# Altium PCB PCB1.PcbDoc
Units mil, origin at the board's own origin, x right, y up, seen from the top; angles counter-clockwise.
Board outline 3995.98 x 2559.06 mil, 2 copper layers (Top Layer, Bottom Layer); 28 components, 42 nets, 154 pads, 4 vias.
Unrouted connection lines stored in the file: 6.
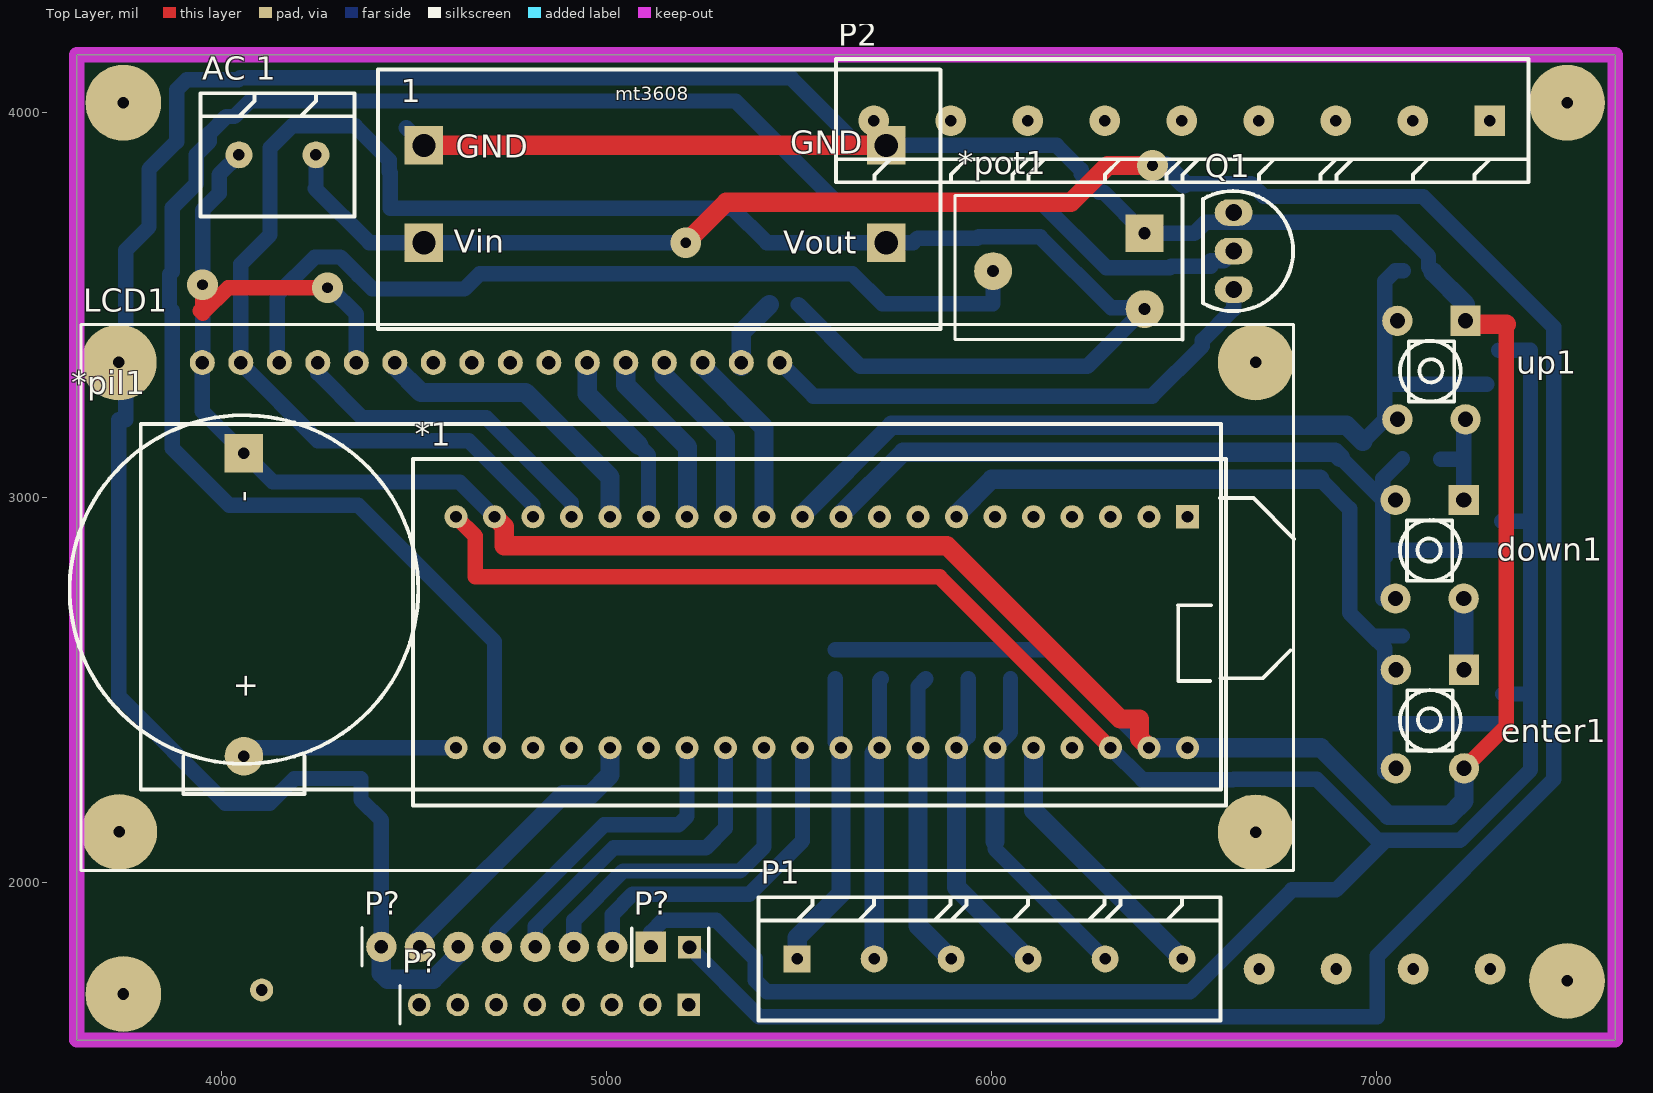
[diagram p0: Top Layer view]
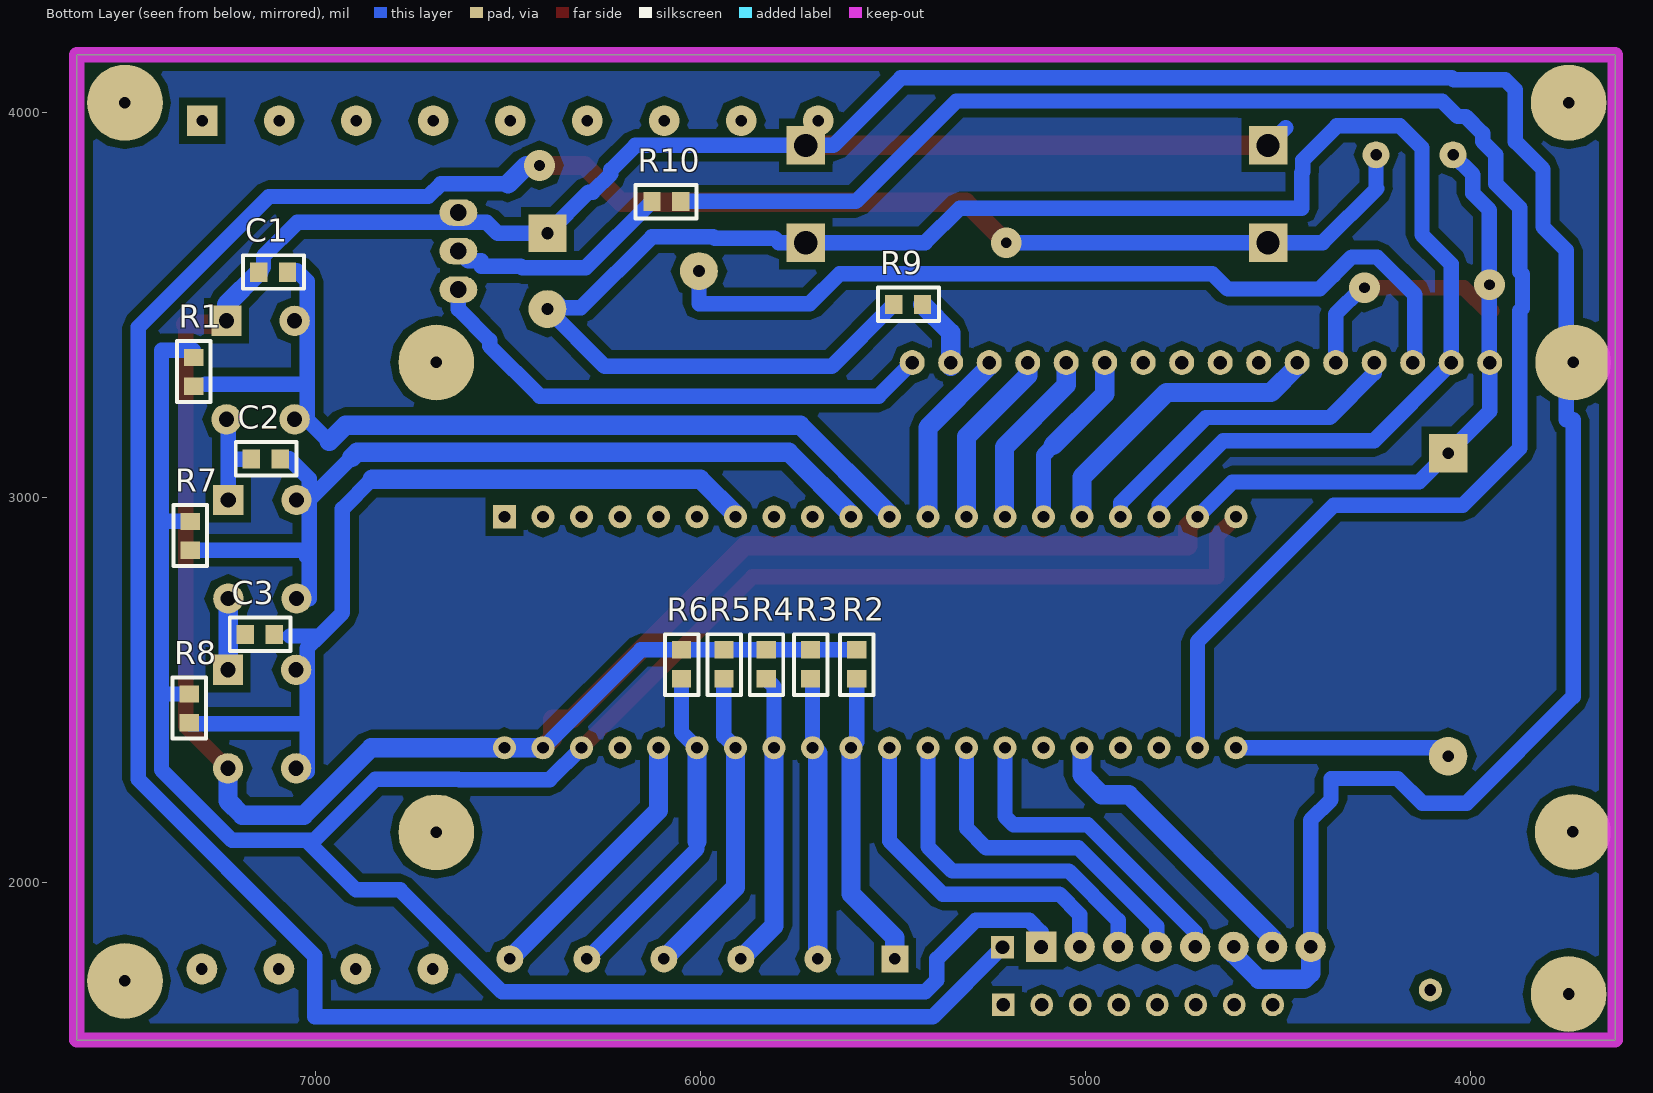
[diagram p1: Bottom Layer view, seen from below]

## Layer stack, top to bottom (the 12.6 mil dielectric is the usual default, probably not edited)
Top Solder: solder mask 0.4, Solder Resist, Dk 3.5
Top Layer: signal copper 1.4
Dielectric 1: dielectric 12.6, FR-4, Dk 4.8
Bottom Layer: signal copper 1.4
Bottom Solder: solder mask 0.4, Solder Resist, Dk 3.5

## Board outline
3624.02,1590.55 3624.02,4149.61 7620,4149.61 7620,1590.55

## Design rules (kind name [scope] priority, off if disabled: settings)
Clearance [All] p1: gap=20
PolygonConnect [All] p1: connectstyle=Relief reliefconductorwidth=10 reliefentries=4 polygonreliefangle="90 Angle" airgapwidth=10
RoutingVias [All] p1: holewidth=28 width=50 viastyle="Through Hole" minholewidth=28 minwidth=50 maxholewidth=28 maxwidth=50
SolderMaskExpansion [All] p1: expansion=4
Width [All] p1: maxlimit=50 minlimit=40 preferedwidth=50
30 further rules are at their usual default settings.

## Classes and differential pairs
component class Sheet2: *1 *pil1 *pot1 C1 C2 C3 down1 enter1 LCD1 P1 P2 P? Q1 R1 R2 R3 R4 R5 R6 R7 R8 R9 R10 up1

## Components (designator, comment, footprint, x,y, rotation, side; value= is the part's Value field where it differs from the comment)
1 "" mt3608 4525.59,3661.42 r0 top
*1 "stm32_blue_pill" STM32_BLUE_PIL 5809.06,2649.61 r180 top
*pil1 "cr2032pil_soket" "cr2032 holder" 4058.23,3115 r270 top
*pot1 "trimpot" trimpot 6397.64,3686.02 r270 top
"AC 1" "" "klemens 200 mil" 4045.28,3889.76 r0 top
C1 "Cap Pol3" "Resistor smd" 7110,3585 r0 bottom
C2 "Cap Pol3" "Resistor smd" 7128.94,3099.41 r0 bottom
C3 "Cap Pol3" "Resistor smd" 7144.69,2643.7 r0 bottom
down1 "buttun 4 pin" button 7137.8,2865.16 r270 top
enter1 "buttun 4 pin" button 7138.78,2424.21 r270 top
LCD1 "162A" lcd_benim_kullndigim 3950,3350 r0 top
P1 "Header 6" "klemens 6X" 5495.08,1801.18 r0 top
P2 "Header 9" "klemens 9X" 7294.29,3978.35 r180 top
P? "Header 8" HDR1X8#1 5213.58,1682.09 r180 top
P? "Header 2" HDR1X2 5215.55,1831.69 r180 top
P? "Header 8" HDR1X8#2 5115.16,1832.68 r180 top
Q1 "BC337" bc337 6628.94,3639.76 r270 top
R1 "Res1" "Resistor smd" 7315.94,3325.79 r270 bottom
R2 "Res1" "Resistor smd" 5594.17,2566.42 r90 bottom
R3 "Res1" "Resistor smd" 5714.17,2566.42 r90 bottom
R4 "Res1" "Resistor smd" 5829.17,2566.42 r90 bottom
R5 "Res1" "Resistor smd" 5939.17,2566.42 r90 bottom
R6 "Res1" "Resistor smd" 6049.17,2566.42 r90 bottom
R7 "Res1" "Resistor smd" 7325,2900 r270 bottom
R8 "Res1" "Resistor smd" 7327.76,2451.77 r270 bottom
R9 "Res1" "Resistor smd" 5460.63,3500.98 r0 bottom
R10 "Res1" "Resistor smd" 6088.58,3768.7 r180 bottom
up1 "buttun 4 pin" button 7142.72,3330.71 r270 top

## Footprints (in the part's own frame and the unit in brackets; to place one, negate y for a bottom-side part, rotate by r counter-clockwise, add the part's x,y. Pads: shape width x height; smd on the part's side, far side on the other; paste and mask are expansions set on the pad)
bc337 [mm]
  oval 1.75x2.5 hole 1.1: 1(-2.54,0) 2(0,0) 3(2.54,0)
  silkscreen extent -3.96,-2.03 3.96,3.92
button [mm]
  rect 2x2 hole 1: 1(-3.25,2.25)
  round 2 hole 1: 2(-3.25,-2.25) 3(3.25,2.25) 4(3.25,-2.25)
  silkscreen extent -1.9,-1.5 2.08,1.5
"cr2032 holder" [mil]
  rect 100x100 hole 30: 1(0,0)
  round 100 hole 30: 2(787.4,0)
  silkscreen extent -98,-453 886,453
HDR1X2 [mm] "Connector; Header; 2 Position"
  rect 1.5x1.5 hole 0.9: 1(0,0)
  round 1.5 hole 0.9: 2(2.54,0)
  silkscreen extent -1.27,-1.27 3.81,1.27
HDR1X8#1 [mm] "Connector; Header; 8 Position"
  rect 1.5x1.5 hole 0.9: 1(0,0)
  round 1.5 hole 0.9: 2(2.54,0) 3(5.08,0) 4(7.62,0) 5(10.16,0) 6(12.7,0) 7(15.24,0) 8(17.78,0)
  silkscreen extent 19.05,-1.27 19.05,1.27
HDR1X8#2 [mm] "Connector; Header; 8 Position"
  rect 2x2 hole 0.9: 1(0,0)
  round 2 hole 0.9: 2(2.54,0) 3(5.08,0) 4(7.62,0) 5(10.16,0) 6(12.7,0) 7(15.24,0) 8(17.78,0)
  silkscreen extent 19.05,-1.27 19.05,1.27
"klemens 6X" [mil]
  rect 70x70 hole 30: 1(0,0)
  round 70 hole 30: 2(200,0) 3(400,0) 4(600,0) 5(800,0) 6(1000,0)
  silkscreen extent -100,-160 1100,160
"klemens 9X" [mil]
  rect 80x80 hole 30: 1(0,0)
  round 80 hole 30: 2(200,0) 3(400,0) 4(600,0) 5(800,0) 6(1000,0) 7(1200,0) 8(1400,0) 9(1600,0)
  silkscreen extent -100,-160 1698,160
"klemens 200 mil" [mil]
  round 70 hole 30: 1(0,0) 2(200,0)
  silkscreen extent -100,-160 300,160
lcd_benim_kullndigim [mil]
  round 65 hole 35.43: 1(0,0) 2(100,0) 3(200,0) 4(300,0) 5(400,0) 6(500,0) 7(600,0) 8(700,0) 9(800,0) 10(900,0) 11(1000,0) 12(1100,0) 13(1200,0) 14(1300,0) 15(1400,0) 16(1500,0)
  silkscreen extent -315,-1319 2836,98
mt3608 [mil] "ayarlý regulatör"
  rect 100x100 hole 60: 1(0,0) 2(0,253) 3(1201,253) 4(1201,0)
  silkscreen extent -119,-224 1342,450
"Resistor smd" [mil]
  rect 45x50 smd: 1(-37.5,0) 2(37.5,0)
  silkscreen extent -80,-44 78,43
STM32_BLUE_PIL [mil] "arduino nano"
  rect 60x60 hole 30: 0(-700,-300)
  round 60 hole 30: 1(-600,-300) 2(-500,-300) 3(-400,-300) 4(-300,-300) 5(-200,-300) 6(-100,-300) 7(0,-300) 8(100,-300) 9(200,-300) 10(300,-300) 11(400,-300) 12(500,-300) 13(600,-300) 14(700,-300) 15(800,-300) 16(900,-300) 17(1000,-300) 18(1100,-300) 19(1200,-300) 20(1200,300) 21(1100,300) 22(1000,300) 23(900,300) 24(800,300) 25(700,300) 26(600,300) 27(500,300) 28(400,300) 29(300,300) 30(200,300) 31(100,300) 32(0,300) 33(-100,300) 34(-200,300) 35(-300,300) 36(-400,300) 37(-500,300) 38(-600,300) 39(-700,300)
  silkscreen extent -800,-450 1312,450
trimpot [mm]
  rect 2.5x2.5 hole 0.8: 1(0,0)
  round 2.5 hole 0.8: 2(2.5,-10) 3(5,0)
  silkscreen extent -2.5,-12.5 7,2.5

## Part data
1: library part "swich up adj regulator modul"
"AC 1": library part klemens2li
C1 C2 C3: "Polarized Capacitor (Surface Mount)"
LCD1: "16 char * 2 line LCD character display with b/light"
P1: "Header, 6-Pin"
P2: "Header, 9-Pin"
P? P?: "Header, 8-Pin"
P?: "Header, 2-Pin"
Q1: "NPN General Purpose Amplifier"
R1 R2 R3 R4 R5 R6 R7 R8 R9 R10: "Resistor"

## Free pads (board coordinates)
  round 196.85 hole 30: 0(7495,4025) 1(7495.08,1744.09) 2(3745,1710) 3(3745,4025) 4(6686.02,2129.92) 5(3734.25,2130.91) 6(3733.27,3350.39) 9(6686.02,3350.39)
  round 80 hole 30: 12(7295,1775) 13(7095,1775) 14(6895,1775) 15(6695,1775)
  round 60 hole 30: 13(4104.33,1720.47)

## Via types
v1: diameter 80, hole 28, Top Layer to Bottom Layer, 4 vias

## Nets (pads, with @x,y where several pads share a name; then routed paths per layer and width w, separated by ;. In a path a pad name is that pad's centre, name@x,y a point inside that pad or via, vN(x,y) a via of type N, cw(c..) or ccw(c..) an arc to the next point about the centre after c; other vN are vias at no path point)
BUTTON_DOWN: *1.9 C2.1 down1.2 down1.4 R7.2 | length 2227.6
  Bottom Layer w40: 6906.02,3103.35 down1.2@7016.42,2992.95 ; down1.4@7016.42,2737.05 7016.42,2855 ; 7023.92,2847.5 7016.42,2855 ; 7023.92,2862.5 R7.2 ; 7067.5,3100 7016.42,3048.92 down1.2@7016.42,2992.95 ; 7016.42,2855 down1.2@7016.42,2992.95
  Bottom Layer w50: *1.9 5609.06,2955.67 5770.63,3117.24 6892.13,3117.24 6906.02,3103.35
BUTTON_ENTER: *1.6 C3.1 enter1.2 enter1.4 R8.2 | length 2200.9
  Bottom Layer w40: 6852.76,3047.24 6930,2970 6930,2700 6990,2640 ; enter1.4@7021.42,2287.05 7021.42,2410 ; 7067.5,2640 6990,2640 ; R8.2@7325.98,2412.5 7023.92,2412.5 7021.42,2410 ; 6990,2640 7021.42,2608.58 7021.42,2410
  Bottom Layer w50: *1.6 5909.06,2955.67 6000.63,3047.24 6852.76,3047.24
BUTTON_UP: *1.10 C1.1 R1.2 up1.2 up1.4 | length 2336.3
  Bottom Layer w40: 6964.37,3145 7021.42,3202.05 7021.42,3561.42 7048.58,3588.58 C1.1@7068.92,3588.58 ; 7026.42,3300 7032.13,3294.29 7286.79,3294.29
  Bottom Layer w50: *1.10 5509.06,2955.67 5740.63,3187.24 6922.13,3187.24 6964.37,3145
DEV_POMP_ROLE: *1.24 P?.7 | length 763
  Bottom Layer w50: P?.7@4515.16,1832.68 4515.16,1855.71 4887.3,2227.85 4958.17,2227.85 5009.06,2278.74 *1.24
DIREK_DEV_POMP_ROLE: *1.29 P?.2@5015.16,1832.68 P?.2@5113.58,1682.09 | length 899
  Bottom Layer w40: P?.2@5015.16,1832.68 5015.16,1916.64 5067.97,1969.45 5371.02,1969.45 5509.06,2107.48 *1.29
DIREK_DEVRE_NTC: *1.30 P1.1 R2.1 | length 781.1
  Bottom Layer w40: R2.1 5594.17,2364.49 *1.30
  Bottom Layer w50: P1.1 5495.08,1856.5 5609.06,1970.47 *1.30
DIS_HAVA_NTC: *1.34 P1.5 R6.1 | length 862.8
  Bottom Layer w40: 6009.06,2106.3 6009.06,2087.2 P1.5 ; *1.34 6049.17,2389.72 R6.1
  Bottom Layer w50: 6009.06,2106.3 *1.34
GND: 1.2 1.3 "AC 1.1" *1.18 *1.38 *1.39 *pil1.1 *pot1.1 C1.2 enter1.3 LCD1.1 LCD1.5 P?.6@4615.16,1832.68 P?.8@4415.16,1832.68 pad.6 Q1.1 R2.2 R3.2 R4.2 R5.2 R6.2 up1.1 | length 15622.4
  Top Layer w40: v1(3950.79,3552.17) 3950.79,3490.16 3944.88,3484.25 3950.79,3478.35 4016.73,3544.29 v1(4275.59,3544.29) ; enter1.3 7337.05,2405.94 7337.05,3449.8
  Top Layer w50: 1.2 1.3 ; *1.18 4734.06,2924.61 4734.06,2874.61 5884.06,2874.61 6334.06,2424.61 6384.06,2424.61 6384.06,2374.61 *1.38 ; up1.1 7240.16,3449.8 7337.05,3449.8
  Bottom Layer w40: LCD1.1@3945.87,3354.13 3944.88,3355.12 3950.79,3361.02 v1(3950.79,3552.17) 3950.79,3746.21 3993.88,3789.3 3993.88,3838.37 4045.28,3889.76 ; LCD1.1 3950,3223.23 *pil1.1 4133.27,3039.96 4618.7,3039.96 *1.18 ; v1(4275.59,3544.29) 4281.5,3544.29 4350,3475.79 LCD1.5 ; P?.8@4415.16,1832.68 4415.16,2161.42 4362.2,2214.37 4362.2,2269.68 4189.17,2269.68 4125,2205.51 4010.04,2205.51 3733.27,2482.28 3733.27,3201.77 3750.98,3201.77 3750.98,3641.73 3811.69,3702.44 3811.69,3852.46 3883.43,3924.19 3883.43,4058.58 3909.49,4084.65 4043.88,4084.65 4048.84,4089.61 5479.69,4089.61 5654.87,3914.42 1.3 6169.24,3914.42 6232.99,3850.67 6232.99,3839.89 6279.86,3793.03 6290.63,3793.03 *pot1.1 6526.96,3686.02 6555.15,3714.21 7047.36,3714.21 7135,3626.57 7135,3597.5 C1.2 ; 1.2@4479.46,3960.55 1.2 ; R2.2 R3.2 R4.2 R5.2 R6.2 6154.74,2603.92 *1.38
  Bottom Layer w50: P?.8@4415.16,1832.68 4415.16,1763.94 4430.79,1748.31 4550.1,1748.31 4615.16,1813.36 P?.6@4615.16,1832.68 ; *1.38 *1.39 6855.12,2349.61 7030.51,2174.21 7189.96,2174.21 7227.36,2211.61 enter1.3 ; C1.2 7231.3,3501.2 up1.1
JD_VCC: 1.1 "AC 1.2" P?.1@5215.55,1831.69 | length 7460.8
  Top Layer w50: v1(5205.71,3661.42) 5311.02,3766.73 6206.69,3766.73 6302.17,3862.2 v1(6418.31,3862.2)
  Bottom Layer w40: 4243.31,3802.17 4384.06,3661.42 1.1 v1(5205.71,3661.42) ; 4245.28,3804.13 4245.28,3889.76 ; P?.1@5215.55,1831.69 5396.69,1650.55 7001.97,1650.55 7001.97,1809.44 7460,2267.47 7460,3442.5 7121.03,3781.47 6707.28,3781.47 6674.54,3814.21 6500,3814.21
  Bottom Layer w50: v1(6418.31,3862.2) 6452.01,3862.2 6500,3814.21
KARISIM_NTC: *1.32 P1.3 R4.1 | length 771.7
  Bottom Layer w40: *1.32 5809.06,2508.8 R4.1
  Bottom Layer w50: *1.32 5809.06,1887.2 P1.3
KAZAN_NTC: *1.33 P1.4 R5.1 | length 817.3
  Bottom Layer w40: *1.33 5939.17,2379.72 R5.1
  Bottom Layer w50: *1.33 5909.06,1987.2 P1.4
KAZAN_ROLE: *1.25
LCD_LED: *1.21 R10.2 | length 4410.3
  Bottom Layer w40: *1.21 4709.06,2625.59 4354.69,2979.96 4019.69,2979.96 3871.69,3127.95 3871.69,3484.66 3864.88,3491.47 3864.88,3579.4 3871.69,3586.21 3871.69,3751.97 3933.88,3814.15 3933.88,3889.79 3968.31,3924.22 3968.31,3945.44 4012.24,3989.37 4033.45,3989.37 4073.69,4029.61 5335.55,4029.61 5596.46,3768.7 R10.2
Net*1_11: *1.11 LCD1.14 | length 456.7
  Bottom Layer w50: LCD1.14@5250,3340.4 5409.06,3181.34 *1.11
Net*1_12: *1.12 LCD1.13 | length 456.7
  Bottom Layer w50: LCD1.13@5150,3340.4 5150,3316.54 5309.06,3157.48 *1.12
Net*1_13: *1.13 LCD1.12 | length 467.6
  Bottom Layer w50: LCD1.12 5050,3291.71 5210.63,3131.08 5210.63,2951.18 *1.13
Net*1_14: *1.14 LCD1.11 | length 466.3
  Bottom Layer w40: 5084.06,3134.45 5109.06,3109.45 *1.14
  Bottom Layer w50: LCD1.11 4950,3268.5 5084.06,3134.45
Net*1_15: *1.15 LCD1.6 | length 791.1
  Bottom Layer w50: LCD1.6 4450,3340.4 4517.9,3272.5 4789.51,3272.5 5009.06,3052.95 *1.15
Net*1_16: *1.16 LCD1.4 | length 862
  Bottom Layer w40: LCD1.4 4250,3322.66 4365.16,3207.5 4687.19,3207.5 4909.06,2985.63 *1.16
Net*1_20: *1.20 *pil1.2 | length 559.9
  Bottom Layer w40: *pil1.2 4080.24,2349.61 *1.20
NetC2_2: C2.2 down1.1 up1.3 | length 258.8
  Bottom Layer w40: C2.2 7213.58,3099.41 ; down1.1 7226.38,3197.83 up1.3
NetC3_2: C3.2 down1.3 enter1.1 | length 184.1
  Bottom Layer w50: enter1.1@7226.38,2553.15 down1.3
NetLCD1_15: LCD1.15 R9.1 | length 190.9
  Bottom Layer w50: LCD1.15@5350,3340.4 LCD1.15 5350,3427.85 R9.1
NetLCD1_16: LCD1.16 Q1.3 | length 1368.2
  Bottom Layer w40: LCD1.16 5537.2,3262.8 6417.32,3262.8 6547.6,3393.07 6547.6,3407.73 6628.69,3488.82 6628.94,3488.82 Q1.3
NetP2_1: P2.1
NetP2_2: P2.2
NetP2_3: P2.3
NetP2_4: P2.4
NetP2_5: P2.5
NetP2_6: P2.6
NetP2_7: P2.7
NetP2_8: P2.8
NetP2_9: P2.9
NetQ1_2: Q1.2 R10.1 | length 600.2
  Bottom Layer w40: R10.1 6297.97,3596.81 6463.42,3596.81 6466.56,3599.95 6569.07,3599.95 6569.07,3614.21 6603.39,3614.21 Q1.2
NTC_ENABLE: *1.35 P1.6 | length 708.3
  Bottom Layer w50: *1.35 6109.06,2187.2 P1.6
POT: *pot1.2 LCD1.3 | length 2246
  Bottom Layer w40: LCD1.3 4144.69,3355.32 4144.69,3526.52 4242.45,3624.29 4308.73,3624.29 4355.59,3577.43 4360.51,3572.51 4391.68,3541.34 4630.91,3541.34 4670.28,3580.71 5638.78,3580.71 5716.54,3502.95 6003.94,3502.95 *pot1.2
SICAK_SU_NTC: *1.31 P1.2 R3.1 | length 735.6
  Bottom Layer w40: *1.31 5709.06,2523.8 R3.1
  Bottom Layer w50: P1.2 5695.08,2335.63 *1.31
SICAK_SU_ROLE: *1.28 P?.3 | length 899
  Bottom Layer w40: P?.3@4915.16,1832.68 4915.16,1901.49 5043.11,2029.45 5346.17,2029.45 5409.06,2092.33 *1.28
VANA_EN_ROLE: *1.27 P?.4 | length 861.9
  Bottom Layer w40: P?.4@4815.16,1832.68 4815.16,1886.34 5018.26,2089.45 5257.87,2089.45 5309.06,2140.63 *1.27
VANA_YON_ROLE: *1.26 P?.5 | length 834.8
  Bottom Layer w40: P?.5@4715.16,1832.68 4715.16,1871.2 4993.41,2149.45 5186.85,2149.45 5209.06,2171.65 *1.26
VCC: *1.19 *1.37 P?.1@5115.16,1832.68 P?.1@5213.58,1682.09 P?.2@5115.55,1831.69 R1.1 R7.1 R8.1 | length 6825.7
  Top Layer w40: *1.19 4659.06,2899.61 4659.06,2793.31 5865.35,2793.31 *1.37
  Bottom Layer w40: P?.2@5115.16,1832.68 5115.16,1870.35 5146.02,1901.22 5285.08,1901.22 5384.13,1802.17 5385.83,1802.17 5385.83,1746.27 5416.55,1715.55 6515.51,1715.55 6780.28,1980.32 6894.72,1980.32 7023.62,2109.21 ; *1.37 6391.93,2266.73 6627.07,2266.73 6628.69,2268.35 6844.45,2268.35 7003.59,2109.21 7023.62,2109.21 ; R1.1@7317.5,3382.5 7400,3382.5 7400,2292.32 7216.88,2109.21 7023.62,2109.21 ; R7.1 7397.5,2937.5 ; R8.1 7398.13,2489.27
VIN: 1.4 *1.17 *pot1.3 LCD1.2 R9.2 | length 5151.9
  Bottom Layer w40: *1.17 4809.06,2980.18 4641.73,3147.5 4249.97,3147.5 4050,3347.47 LCD1.2 4050,3606.1 4125.98,3682.09 4125.98,3907.6 4183.15,3964.76 4347.24,3964.76 4435.59,3876.42 4435.59,3845.45 4437.99,3843.05 4437.99,3751.42 5326.34,3751.42 5416.34,3661.42 1.4 5796.26,3661.42 5808.07,3673.23 5963.4,3673.23 5966.98,3676.81 6126.13,3676.81 6310.19,3492.75 6359.9,3492.75 6376.98,3509.83 *pot1.3 6249.02,3340.55 5658.56,3340.55 R9.2
pads on no net: *1.0 *1.1 *1.2 *1.3 *1.4 *1.5 *1.7 *1.8 *1.22 *1.23 *1.36 LCD1.7 LCD1.8 LCD1.9 LCD1.10 P?.6@4713.58,1682.09 P?.8@4513.58,1682.09

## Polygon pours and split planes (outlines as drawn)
no net on Bottom Layer "Bottom Layer-No Net" (solid, pour order 11): 3624.02,4149.61 7620,4149.61 7620,1590.55 3625.98,1590.55 3623.03,1593.5

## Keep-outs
Keep-Out Layer:
  the board outline again, w40

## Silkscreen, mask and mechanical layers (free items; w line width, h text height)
Top Overlay:
  lines w10: 7218.66,2416.18 cw(c7139.76,2420.28) 7218.77,2420.28 ; 7218.66,2858.11 cw(c7139.76,2862.2) 7218.77,2862.2 ; 7218.66,3323.66 cw(c7139.76,3327.76) 7218.77,3327.76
